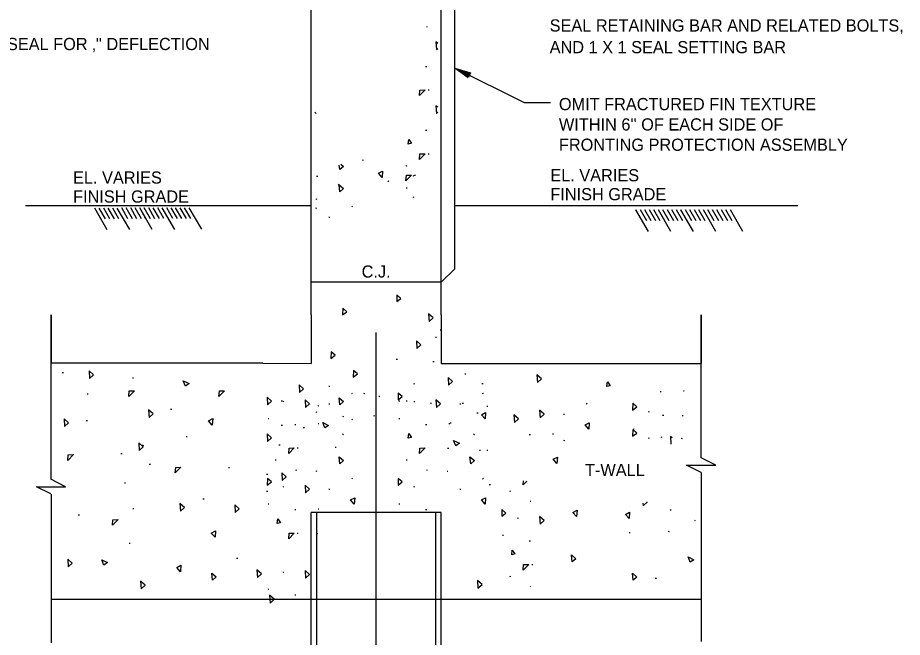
# Model space of a CAD drawing. Extents: x 22369.6 to 22389.4, y 22369.6 to 22386.
# Drawn here: x 22376.584 to 22379.986, y 22375.08 to 22377.463 of the extents above; entities that cross this region are included whole.
import ezdxf

# ---------------------------------------------------------------- set-up
doc = ezdxf.new("R2010")
doc.units = 0
for name, color, linetype in [('Level 1', 7, 'Continuous'), ('Level 2', 7, 'Continuous'), ('Level 3', 7, 'Continuous'), ('Level 4', 7, 'Continuous'), ('Level 44', 7, 'Continuous'), ('Level 7', 7, 'Continuous')]:
    doc.layers.add(name, color=color, linetype=linetype)

msp = doc.modelspace()

# ---------------------------------------------------------------- linework, layer by layer
at = {"layer": 'Level 1'}
for p, q in [((22376.9288, 22376.6477), (22376.8804, 22376.7308)), ((22376.9046, 22376.6893), (22376.8804, 22376.7308)), ((22376.9219, 22376.6893), (22376.8977, 22376.7309)), ((22376.9392, 22376.6894), (22376.915, 22376.7309)), ((22376.9565, 22376.6895), (22376.9323, 22376.731)), ((22376.9738, 22376.6895), (22376.9496, 22376.7311)), ((22377.0153, 22376.6481), (22376.9669, 22376.7311)), ((22376.9911, 22376.6896), (22376.9669, 22376.7311)), ((22377.0084, 22376.6897), (22376.9842, 22376.7312)), ((22377.0257, 22376.6897), (22377.0016, 22376.7313)), ((22377.043, 22376.6898), (22377.0188, 22376.7313)), ((22377.0603, 22376.6899), (22377.0361, 22376.7314)), ((22377.0776, 22376.69), (22377.0534, 22376.7315)), ((22377.1018, 22376.6484), (22377.0535, 22376.7315)), ((22377.0949, 22376.69), (22377.0707, 22376.7316)), ((22377.1122, 22376.6901), (22377.0881, 22376.7316)), ((22377.1295, 22376.6902), (22377.1053, 22376.7317)), ((22377.1468, 22376.6902), (22377.1226, 22376.7318)), ((22377.1883, 22376.6488), (22377.1399, 22376.7318)), ((22377.1814, 22376.6904), (22377.1572, 22376.7319)), ((22377.1987, 22376.6904), (22377.1746, 22376.732)), ((22377.2161, 22376.6905), (22377.1918, 22376.732)), ((22377.2333, 22376.6906), (22377.2091, 22376.7321)), ((22377.2506, 22376.6906), (22377.2264, 22376.7322)), ((22377.2922, 22376.6492), (22377.2438, 22376.7322)), ((22379.0101, 22376.6402), (22378.962, 22376.7235)), ((22378.986, 22376.6818), (22378.962, 22376.7235)), ((22379.0033, 22376.6819), (22378.9793, 22376.7235)), ((22379.0206, 22376.6819), (22378.9966, 22376.7235)), ((22379.0379, 22376.6819), (22379.0139, 22376.7235)), ((22379.0552, 22376.6819), (22379.0312, 22376.7235)), ((22379.0966, 22376.6403), (22379.0485, 22376.7235)), ((22379.0725, 22376.6819), (22379.0485, 22376.7235)), ((22379.0899, 22376.6819), (22379.0658, 22376.7235)), ((22379.1072, 22376.6819), (22379.0832, 22376.7235)), ((22379.1245, 22376.6819), (22379.1004, 22376.7235)), ((22379.1418, 22376.6819), (22379.1178, 22376.7235)), ((22379.159, 22376.6819), (22379.135, 22376.7235)), ((22379.1831, 22376.6403), (22379.1351, 22376.7235)), ((22379.1764, 22376.6819), (22379.1523, 22376.7235)), ((22379.1937, 22376.6819), (22379.1697, 22376.7235)), ((22379.211, 22376.6819), (22379.1869, 22376.7235)), ((22379.2283, 22376.6819), (22379.2043, 22376.7235)), ((22379.2696, 22376.6403), (22379.2215, 22376.7235)), ((22379.2629, 22376.6819), (22379.2388, 22376.7235)), ((22379.2802, 22376.6819), (22379.2562, 22376.7235)), ((22379.2975, 22376.6819), (22379.2735, 22376.7235)), ((22379.3148, 22376.6819), (22379.2908, 22376.7235)), ((22379.3321, 22376.6819), (22379.308, 22376.7236)), ((22379.3735, 22376.6403), (22379.3254, 22376.7236)), ((22377.9633, 22373.7951), (22377.9633, 22376.2524))]:
    msp.add_line(p, q, dxfattribs=at)
for points in [[(22379.2133, 22375.7136), (22379.157, 22375.7415), (22379.2694, 22375.7415), (22379.2133, 22375.7698)], [(22376.7123, 22375.6313), (22376.656, 22375.6593), (22376.7684, 22375.6593), (22376.7123, 22375.6876)]]:
    msp.add_lwpolyline(points, dxfattribs=at)
at = {"layer": 'Level 2'}
for p, q in [((22378.2657, 22377.269), (22378.2657, 22377.269)), ((22378.2812, 22377.2613), (22378.2812, 22377.2613)), ((22378.2133, 22376.4457), (22377.7133, 22376.4457)), ((22376.7133, 22375.6871), (22376.7133, 22376.3207)), ((22376.7133, 22376.3207), (22376.7133, 22376.1337)), ((22377.7133, 22376.3207), (22377.7133, 22376.1337)), ((22378.2133, 22376.3207), (22378.2133, 22376.1333)), ((22379.2133, 22375.7698), (22379.2133, 22376.3207)), ((22379.2133, 22376.3207), (22379.2133, 22376.1333)), ((22377.5264, 22376.1338), (22376.7133, 22376.1338)), ((22377.5264, 22376.1338), (22377.7133, 22376.1337)), ((22378.2133, 22376.1333), (22378.4008, 22376.1332)), ((22378.4008, 22376.1332), (22379.2133, 22376.1332)), ((22379.2133, 22375.7136), (22379.2133, 22375.0639)), ((22376.7133, 22375.6308), (22376.7133, 22375.0592)), ((22378.2133, 22375.5604), (22377.7133, 22375.5604)), ((22377.7133, 22374.4108), (22377.7133, 22375.5604)), ((22377.7341, 22373.7852), (22377.7341, 22375.5604)), ((22378.1925, 22373.7852), (22378.1925, 22375.5604)), ((22378.2133, 22373.7852), (22378.2133, 22375.5604)), ((22379.2133, 22375.225), (22376.7133, 22375.225))]:
    msp.add_line(p, q, dxfattribs=at)
for points in [[(22378.634, 22377.1361), (22378.5331, 22377.1361), (22378.2657, 22377.269)], [(22378.3169, 22377.232), (22378.2657, 22377.269), (22378.3261, 22377.2505), (22378.3182, 22377.2347), (22378.2812, 22377.2613), (22378.3222, 22377.2487), (22378.3172, 22377.2386), (22378.2961, 22377.2539), (22378.3183, 22377.2469), (22378.3163, 22377.2427), (22378.3116, 22377.2461)]]:
    msp.add_lwpolyline(points, dxfattribs=at)
at = {"layer": 'Level 3'}
for p, q in [((22377.7133, 22376.7396), (22376.6138, 22376.7396)), ((22379.5842, 22376.7396), (22378.2654, 22376.7396))]:
    msp.add_line(p, q, dxfattribs=at)
at = {"layer": 'Level 44'}
for p, q in [((22378.156, 22377.4294), (22378.1593, 22377.4281)), ((22378.153, 22377.2759), (22378.1575, 22377.2759)), ((22378.1626, 22377.1858), (22378.1669, 22377.1858)), ((22378.153, 22377.0303), (22378.1575, 22377.0303)), ((22377.9086, 22376.9166), (22377.9126, 22376.9146)), ((22378.1626, 22376.9401), (22378.1669, 22376.9401)), ((22378.0778, 22376.8936), (22378.0821, 22376.8943)), ((22377.734, 22376.8536), (22377.7385, 22376.8536)), ((22378.104, 22376.8558), (22378.1072, 22376.8546)), ((22378.1105, 22376.8579), (22378.1148, 22376.8579)), ((22377.8166, 22376.8205), (22377.8204, 22376.8227)), ((22378.008, 22376.8329), (22378.0118, 22376.8351)), ((22378.0778, 22376.8086), (22378.0821, 22376.8093)), ((22377.7304, 22376.7663), (22377.7349, 22376.7651)), ((22378.104, 22376.7735), (22378.1072, 22376.7723)), ((22377.7304, 22376.7307), (22377.7349, 22376.7319)), ((22377.8687, 22376.7355), (22377.8725, 22376.7377)), ((22377.7814, 22376.6965), (22377.785, 22376.6961)), ((22378.1906, 22376.2349), (22378.1951, 22376.2349)), ((22378.2094, 22376.2631), (22378.2139, 22376.2631)), ((22378.0401, 22376.1502), (22378.0446, 22376.1502)), ((22378.1812, 22376.1407), (22378.1857, 22376.1407)), ((22376.7557, 22376.098), (22376.7602, 22376.098)), ((22377.0256, 22376.0775), (22377.0301, 22376.0775)), ((22378.3035, 22376.0937), (22378.308, 22376.0937)), ((22377.7814, 22376.0465), (22377.785, 22376.0462)), ((22378.108, 22376.0545), (22378.1115, 22376.0562)), ((22378.3693, 22376.056), (22378.3738, 22376.056)), ((22376.8513, 22376.016), (22376.8558, 22376.016)), ((22377.8687, 22376.0171), (22377.8725, 22376.0194)), ((22377.914, 22376.0195), (22377.918, 22376.0175)), ((22377.973, 22376.0084), (22377.977, 22376.0064)), ((22378.372, 22376.0171), (22378.3758, 22376.0194)), ((22379.0549, 22376.025), (22379.0594, 22376.025)), ((22379.1446, 22376.0279), (22379.1479, 22376.0285)), ((22377.598, 22375.9901), (22377.6025, 22375.9901)), ((22377.6046, 22375.9861), (22377.6082, 22375.9878)), ((22377.7393, 22375.9703), (22377.7426, 22375.9709)), ((22377.7814, 22375.9781), (22377.785, 22375.9778)), ((22378.0504, 22375.9898), (22378.0537, 22375.99)), ((22378.0778, 22375.9893), (22378.0821, 22375.99)), ((22378.108, 22375.9861), (22378.1115, 22375.9878)), ((22378.1718, 22375.9807), (22378.1763, 22375.9807)), ((22378.2847, 22375.9781), (22378.2884, 22375.9778)), ((22378.2941, 22375.9807), (22378.2986, 22375.9807)), ((22378.3881, 22375.9686), (22378.3926, 22375.9686)), ((22378.7706, 22375.9778), (22378.7744, 22375.98)), ((22377.1725, 22375.958), (22377.177, 22375.958)), ((22377.7304, 22375.947), (22377.7349, 22375.9458)), ((22377.8336, 22375.931), (22377.8376, 22375.929)), ((22377.9545, 22375.9313), (22377.9582, 22375.9335)), ((22378.3505, 22375.943), (22378.355, 22375.943)), ((22378.6833, 22375.9388), (22378.687, 22375.9385)), ((22379.0099, 22375.9468), (22379.0135, 22375.9485)), ((22379.0646, 22375.9349), (22379.0688, 22375.9349)), ((22379.1392, 22375.9333), (22379.1437, 22375.9333)), ((22376.8479, 22375.9135), (22376.8524, 22375.9135)), ((22377.547, 22375.9214), (22377.5504, 22375.9216)), ((22377.598, 22375.896), (22377.6025, 22375.896)), ((22377.6496, 22375.899), (22377.6541, 22375.899)), ((22377.7393, 22375.9019), (22377.7426, 22375.9025)), ((22377.8687, 22375.9162), (22377.8725, 22375.9185)), ((22378.0504, 22375.9214), (22378.0537, 22375.9216)), ((22378.153, 22375.899), (22378.1575, 22375.899)), ((22378.2426, 22375.9019), (22378.246, 22375.9025)), ((22378.247, 22375.9054), (22378.2515, 22375.9054)), ((22377.6826, 22375.8865), (22377.6871, 22375.8865)), ((22377.8336, 22375.8626), (22377.8376, 22375.8606)), ((22378.337, 22375.8626), (22378.341, 22375.8606)), ((22378.5515, 22375.8597), (22378.556, 22375.8597)), ((22378.6412, 22375.8625), (22378.6445, 22375.8631)), ((22378.9523, 22375.882), (22378.9556, 22375.8823)), ((22377.2316, 22375.852), (22377.2361, 22375.852)), ((22378.6833, 22375.8379), (22378.687, 22375.8375)), ((22379.0099, 22375.8459), (22379.0135, 22375.8475)), ((22379.058, 22375.8505), (22379.0612, 22375.8493)), ((22379.1356, 22375.846), (22379.1401, 22375.8448)), ((22377.0636, 22375.8199), (22377.0676, 22375.8179)), ((22377.5886, 22375.8206), (22377.5931, 22375.8206)), ((22377.6593, 22375.8089), (22377.6635, 22375.8089)), ((22377.8049, 22375.8112), (22377.8094, 22375.8112)), ((22378.1626, 22375.8089), (22378.163, 22375.8089)), ((22378.2373, 22375.8073), (22378.2418, 22375.8073)), ((22378.3599, 22375.7992), (22378.3644, 22375.7992)), ((22378.3881, 22375.7992), (22378.3926, 22375.7992)), ((22376.9811, 22375.7871), (22376.9856, 22375.7871)), ((22377.5745, 22375.7623), (22377.5788, 22375.763)), ((22378.0778, 22375.7623), (22378.0821, 22375.763)), ((22377.0905, 22375.7461), (22377.095, 22375.7461)), ((22377.3945, 22375.7325), (22377.399, 22375.7325)), ((22377.6527, 22375.7245), (22377.656, 22375.7233)), ((22378.156, 22375.7245), (22378.1593, 22375.7233)), ((22377.5415, 22375.7077), (22377.546, 22375.7077)), ((22377.7304, 22375.72), (22377.7349, 22375.7188)), ((22377.8687, 22375.6892), (22377.8725, 22375.6915)), ((22378.2354, 22375.7195), (22378.2382, 22375.7188)), ((22378.372, 22375.6892), (22378.3758, 22375.6915)), ((22376.9956, 22375.6747), (22376.9993, 22375.6744)), ((22377.6046, 22375.6582), (22377.6082, 22375.6599)), ((22378.108, 22375.6582), (22378.1115, 22375.6599)), ((22378.3975, 22375.6674), (22378.402, 22375.6674)), ((22377.5415, 22375.6418), (22377.546, 22375.6418)), ((22377.7814, 22375.6502), (22377.785, 22375.6499)), ((22378.2847, 22375.6502), (22378.2884, 22375.6499)), ((22378.4764, 22375.642), (22378.4807, 22375.6427)), ((22377.2965, 22375.6129), (22377.301, 22375.6129)), ((22377.547, 22375.5935), (22377.5504, 22375.5937)), ((22378.0504, 22375.5935), (22378.0537, 22375.5937)), ((22378.5546, 22375.6042), (22378.5579, 22375.603)), ((22377.0266, 22375.5753), (22377.0311, 22375.5753)), ((22377.6496, 22375.5711), (22377.6541, 22375.5711)), ((22377.7393, 22375.574), (22377.7426, 22375.5745)), ((22378.153, 22375.5711), (22378.1575, 22375.5711)), ((22379.0932, 22375.5689), (22379.097, 22375.5711)), ((22376.8172, 22375.5514), (22376.8217, 22375.5514)), ((22378.5065, 22375.5379), (22378.5101, 22375.5396)), ((22379.1866, 22375.5299), (22379.1903, 22375.5296)), ((22379.0861, 22375.4885), (22379.0901, 22375.4865)), ((22377.6593, 22375.481), (22377.6635, 22375.481)), ((22377.734, 22375.4794), (22377.7385, 22375.4794)), ((22378.449, 22375.4731), (22378.4523, 22375.4734)), ((22378.5515, 22375.4508), (22378.556, 22375.4508)), ((22378.9353, 22375.4831), (22378.9398, 22375.4831)), ((22377.013, 22375.4421), (22377.0172, 22375.4421)), ((22377.4264, 22375.384), (22377.4306, 22375.384)), ((22378.5612, 22375.3606), (22378.5655, 22375.3606)), ((22377.6046, 22375.3303), (22377.6082, 22375.332)), ((22378.4764, 22375.3141), (22378.4807, 22375.3148)), ((22379.0364, 22375.3069), (22379.0409, 22375.3069)), ((22377.547, 22375.2655), (22377.5504, 22375.2658)), ((22378.5546, 22375.2763), (22378.5564, 22375.2756)), ((22377.6496, 22375.2432), (22377.6541, 22375.2432))]:
    msp.add_line(p, q, dxfattribs=at)
for points in [[(22378.1995, 22377.364), (22378.193, 22377.3699), (22378.1946, 22377.3404)], [(22378.1946, 22377.3404), (22378.1995, 22377.3449)], [(22378.1995, 22377.1184), (22378.193, 22377.1242), (22378.1946, 22377.0947)], [(22377.732, 22377.0947), (22377.7271, 22377.0992)], [(22378.1946, 22377.0947), (22378.1995, 22377.0992)], [(22377.8268, 22376.8997), (22377.8372, 22376.8906), (22377.823, 22376.8787), (22377.8211, 22376.896)], [(22379.1014, 22375.8469), (22379.0949, 22375.8527), (22379.0966, 22375.8232)], [(22378.5427, 22375.6811), (22378.5283, 22375.6664), (22378.5295, 22375.6814)], [(22379.0021, 22375.6015), (22379.0047, 22375.5992), (22378.9906, 22375.5873), (22378.9896, 22375.5956)]]:
    msp.add_lwpolyline(points, dxfattribs=at)
for points in [[(22378.1314, 22377.1847), (22378.1514, 22377.1858), (22378.1297, 22377.1636)], [(22378.0856, 22376.977), (22378.088, 22376.9952), (22378.0982, 22376.98)], [(22378.1314, 22376.9391), (22378.1514, 22376.9401), (22378.1297, 22376.918)], [(22377.986, 22376.8489), (22377.9718, 22376.8649), (22377.9877, 22376.8734)], [(22378.0793, 22376.8568), (22378.0993, 22376.8579), (22378.0776, 22376.8357)], [(22377.8201, 22376.8206), (22377.8372, 22376.8056), (22377.823, 22376.7937)], [(22378.0419, 22376.3711), (22378.0579, 22376.3832), (22378.0426, 22376.3968)], [(22377.8335, 22376.3198), (22377.8495, 22376.3319), (22377.8342, 22376.3455)], [(22378.1664, 22376.2946), (22378.1818, 22376.3088), (22378.1647, 22376.3241)], [(22378.1194, 22376.191), (22378.1348, 22376.2053), (22378.1177, 22376.2205)], [(22377.7891, 22376.1524), (22377.8051, 22376.1645), (22377.7898, 22376.1781)], [(22376.8605, 22376.0755), (22376.8759, 22376.0898), (22376.8588, 22376.105)], [(22377.8745, 22376.0807), (22377.8905, 22376.0928), (22377.8752, 22376.1064)], [(22377.2291, 22376.046), (22377.2212, 22376.0664), (22377.2433, 22376.0556)], [(22378.2417, 22376.0498), (22378.2571, 22376.064), (22378.24, 22376.0793)], [(22378.5828, 22376.0599), (22378.5982, 22376.0741), (22378.5811, 22376.0894)], [(22378.8498, 22376.0445), (22378.8522, 22376.0628), (22378.8624, 22376.0475)], [(22377.6679, 22376.0215), (22377.6833, 22376.0358), (22377.6662, 22376.051)], [(22377.0134, 22376.0274), (22377.0334, 22376.0285), (22377.0118, 22376.0063)], [(22377.3598, 22376.0274), (22377.3798, 22376.0285), (22377.3581, 22376.0063)], [(22377.5456, 22375.9745), (22377.561, 22375.9887), (22377.5439, 22376.004)], [(22377.8201, 22376.0013), (22377.8372, 22375.9864), (22377.823, 22375.9745)], [(22378.0472, 22375.9935), (22378.0632, 22376.0056), (22378.0479, 22376.0192)], [(22377.6913, 22375.9635), (22377.7067, 22375.9777), (22377.6896, 22375.993)], [(22378.1946, 22375.9635), (22378.21, 22375.9777), (22378.193, 22375.993)], [(22378.9491, 22375.9542), (22378.9651, 22375.9663), (22378.9498, 22375.9799)], [(22377.0894, 22375.9252), (22377.1048, 22375.9394), (22377.0877, 22375.9547)], [(22378.3822, 22375.9202), (22378.368, 22375.9362), (22378.3839, 22375.9447)], [(22378.4945, 22375.9058), (22378.51, 22375.9201), (22378.4929, 22375.9353)], [(22378.5932, 22375.9241), (22378.6086, 22375.9384), (22378.5915, 22375.9536)], [(22376.7649, 22375.891), (22376.7803, 22375.9053), (22376.7632, 22375.9205)], [(22377.3327, 22375.8965), (22377.3185, 22375.9125), (22377.3344, 22375.921)], [(22377.7655, 22375.8855), (22377.7575, 22375.9059), (22377.7796, 22375.8951)], [(22378.7808, 22375.8809), (22378.7665, 22375.8969), (22378.7825, 22375.9054)], [(22377.5456, 22375.8332), (22377.561, 22375.8475), (22377.5439, 22375.8627)], [(22378.0856, 22375.8457), (22378.088, 22375.864), (22378.0982, 22375.8487)], [(22378.9491, 22375.8533), (22378.9651, 22375.8654), (22378.9498, 22375.8789)], [(22377.0518, 22375.7988), (22377.0672, 22375.813), (22377.0502, 22375.8283)], [(22378.2688, 22375.817), (22378.2609, 22375.8375), (22378.283, 22375.8267)], [(22377.628, 22375.8078), (22377.648, 22375.8089), (22377.6264, 22375.7867)], [(22378.1314, 22375.8078), (22378.1514, 22375.8089), (22378.1297, 22375.7867)], [(22376.7788, 22375.7816), (22376.7988, 22375.7827), (22376.7771, 22375.7605)], [(22377.8201, 22375.7743), (22377.8372, 22375.7594), (22377.823, 22375.7475)], [(22378.3235, 22375.7743), (22378.3405, 22375.7594), (22378.3264, 22375.7475)], [(22378.6582, 22375.7489), (22378.644, 22375.7649), (22378.6599, 22375.7734)], [(22377.1922, 22375.7332), (22377.2122, 22375.7342), (22377.1905, 22375.7121)], [(22377.5439, 22375.6656), (22377.5599, 22375.6777), (22377.5445, 22375.6913)], [(22377.602, 22375.6826), (22377.6174, 22375.6969), (22377.6004, 22375.7121)], [(22378.0472, 22375.6656), (22378.0632, 22375.6777), (22378.0479, 22375.6913)], [(22377.6913, 22375.6355), (22377.7067, 22375.6498), (22377.6896, 22375.665)], [(22377.2098, 22375.5646), (22377.2252, 22375.5788), (22377.2081, 22375.5941)], [(22377.4208, 22375.5596), (22377.4362, 22375.5739), (22377.4191, 22375.5891)], [(22377.8789, 22375.5923), (22377.8646, 22375.6083), (22377.8805, 22375.6168)], [(22378.3822, 22375.5923), (22378.368, 22375.6083), (22378.3839, 22375.6168)], [(22378.4458, 22375.5453), (22378.4618, 22375.5574), (22378.4465, 22375.571)], [(22378.7336, 22375.5446), (22378.7194, 22375.5606), (22378.7353, 22375.5691)], [(22378.9359, 22375.5366), (22378.9216, 22375.5526), (22378.9375, 22375.5611)], [(22376.9501, 22375.532), (22376.9701, 22375.5331), (22376.9484, 22375.5109)], [(22377.5823, 22375.5178), (22377.5846, 22375.536), (22377.5949, 22375.5208)], [(22378.5932, 22375.5152), (22378.6086, 22375.5295), (22378.5915, 22375.5447)], [(22377.3431, 22375.4649), (22377.3289, 22375.4809), (22377.3448, 22375.4894)], [(22377.628, 22375.4799), (22377.648, 22375.481), (22377.6264, 22375.4588)], [(22378.4842, 22375.3975), (22378.4865, 22375.4157), (22378.4968, 22375.4005)], [(22378.7141, 22375.397), (22378.7312, 22375.3821), (22378.717, 22375.3702)], [(22379.1707, 22375.3688), (22379.1628, 22375.3892), (22379.1849, 22375.3785)], [(22376.7785, 22375.3512), (22376.7939, 22375.3655), (22376.7768, 22375.3807)], [(22376.9157, 22375.3579), (22376.9078, 22375.3783), (22376.9299, 22375.3675)], [(22377.2102, 22375.3324), (22377.1959, 22375.3484), (22377.2118, 22375.3569)], [(22378.53, 22375.3596), (22378.55, 22375.3606), (22378.5283, 22375.3385)], [(22377.3307, 22375.3272), (22377.3478, 22375.3123), (22377.3336, 22375.3003)], [(22377.5062, 22375.3102), (22377.5216, 22375.3245), (22377.5045, 22375.3397)], [(22377.6913, 22375.3076), (22377.7067, 22375.3219), (22377.6896, 22375.3371)], [(22378.9488, 22375.3261), (22378.9658, 22375.3111), (22378.9517, 22375.2992)], [(22377.0587, 22375.2658), (22377.0741, 22375.2801), (22377.057, 22375.2953)], [(22378.3545, 22375.2684), (22378.37, 22375.2826), (22378.3529, 22375.2979)], [(22377.555, 22375.2119), (22377.5704, 22375.2261), (22377.5533, 22375.2414)]]:
    msp.add_lwpolyline(points, close=True, dxfattribs=at)
at = {"layer": 'Level 7'}
for p, q in [((22377.7133, 22376.3207), (22377.7133, 22378.0306)), ((22378.2133, 22376.3207), (22378.2133, 22378.0306)), ((22378.2654, 22376.4978), (22378.2654, 22377.6348)), ((22378.2133, 22376.4457), (22378.2654, 22376.4978))]:
    msp.add_line(p, q, dxfattribs=at)

# ---------------------------------------------------------------- texts
at = {"layer": 'Level 2'}
msp.add_text('T-WALL', height=0.04688, dxfattribs=at).set_placement((22378.766, 22375.7001))
at = {"layer": 'Level 4'}
for s, height, p in [('SEAL RETAINING BAR AND RELATED BOLTS,', 0.046875, (22378.6301, 22377.4098)), ("  SET SEAL FOR ‚'' DEFLECTION", 0.046875, (22376.3689, 22377.3385)), ('AND 1 X 1 SEAL SETTING BAR', 0.046875, (22378.6301, 22377.3264)), ('OMIT FRACTURED FIN TEXTURE', 0.046875, (22378.6657, 22377.1074)), ("WITHIN 6'' OF EACH SIDE OF", 0.046875, (22378.6657, 22377.0292)), ('FRONTING PROTECTION ASSEMBLY', 0.046875, (22378.6657, 22376.9511)), ('EL. VARIES', 0.04688, (22378.6327, 22376.8338)), ('EL. VARIES', 0.04688, (22376.7972, 22376.8248)), ('FINISH GRADE', 0.046875, (22376.7972, 22376.7518)), ('FINISH GRADE', 0.046875, (22378.6327, 22376.7609)), ('C.J.', 0.04688, (22377.9071, 22376.4634))]:
    msp.add_text(s, height=height, dxfattribs=at).set_placement(p)

doc.saveas('drawing.dxf')
